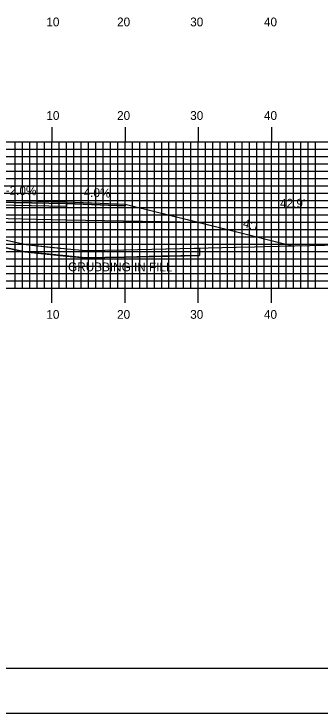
# Model space of a CAD drawing. Extents: x 1823573 to 1823916, y 442591 to 442811.
# Drawn here: x 1823743.1 to 1823784.9, y 442590.5 to 442686.2 of the extents above; entities that cross this region are included whole.
import ezdxf

# ---------------------------------------------------------------- set-up
doc = ezdxf.new("R2010")
doc.units = 0
for name, color, linetype in [('ANNOTATION', 7, 'Continuous'), ('BORDER', 7, 'Continuous'), ('D_Roadway_Centerline', 7, 'Continuous'), ('D_Roadway_Edge_Shoulder', 7, 'Continuous'), ('D_Roadway_Edge_TW', 7, 'Continuous'), ('D_Roadway_Pavement', 7, 'Continuous'), ('D_Roadway_SlopeLines', 7, 'Continuous'), ('D_Roadway_SubGrade', 7, 'Continuous'), ('D_Text_Standard', 7, 'Continuous'), ('GRUBBING IN FILL', 7, 'Continuous'), ('H_V ANNOTATION', 7, 'Continuous'), ('MAJOR', 7, 'Continuous'), ('MINOR', 7, 'Continuous'), ('PLOT BOUNDARY', 7, 'Continuous'), ('S_Roadway_Centerline', 7, 'Continuous')]:
    doc.layers.add(name, color=color, linetype=linetype)

msp = doc.modelspace()

# ---------------------------------------------------------------- linework, layer by layer
at = {"layer": 'BORDER'}
msp.add_lwpolyline([(1823588.709, 442596.665), (1823908.709, 442596.665), (1823908.709, 442806.665), (1823588.709, 442806.665)], close=True, dxfattribs=at)
at = {"layer": 'D_Roadway_Centerline'}
msp.add_lwpolyline([(1823662.489, 442655.78), (1823704.135, 442656.613), (1823708.135, 442657.613), (1823718.309, 442660.156), (1823726.309, 442660.476), (1823738.309, 442660.716), (1823750.309, 442660.476), (1823758.309, 442660.156), (1823768.483, 442657.613), (1823772.483, 442656.613), (1823781.16, 442654.443)], dxfattribs=at)
at = {"layer": 'D_Roadway_Edge_Shoulder'}
msp.add_lwpolyline([(1823750.309, 442660.476), (1823758.309, 442660.156), (1823758.309, 442659.906), (1823750.309, 442660.226)], close=True, dxfattribs=at)
at = {"layer": 'D_Roadway_Edge_TW'}
msp.add_lwpolyline([(1823726.309, 442660.226), (1823726.309, 442660.476), (1823738.309, 442660.716), (1823750.309, 442660.476), (1823750.309, 442660.226), (1823738.309, 442660.466)], close=True, dxfattribs=at)
at = {"layer": 'D_Roadway_Pavement'}
msp.add_lwpolyline([(1823726.309, 442659.81), (1823726.309, 442660.226), (1823738.309, 442660.466), (1823750.309, 442660.226), (1823750.309, 442659.81), (1823738.309, 442660.05)], close=True, dxfattribs=at)
at = {"layer": 'D_Roadway_SlopeLines'}
msp.add_lwpolyline([(1823758.309, 442660.156), (1823772.483, 442656.613), (1823781.16, 442654.443)], dxfattribs=at)
at = {"layer": 'D_Roadway_SubGrade'}
msp.add_lwpolyline([(1823726.309, 442657.976), (1823708.135, 442657.613), (1823718.309, 442660.156), (1823718.309, 442659.906), (1823726.309, 442660.226), (1823738.309, 442660.466), (1823750.309, 442660.226), (1823758.309, 442659.906), (1823758.309, 442660.156), (1823768.483, 442657.613), (1823750.309, 442657.976), (1823738.309, 442658.216)], close=True, dxfattribs=at)
at = {"layer": 'GRUBBING IN FILL'}
msp.add_line((1823768.483, 442654.139), (1823768.483, 442653.139), dxfattribs=at)
msp.add_line((1823768.483, 442654.139), (1823768.483, 442653.139), dxfattribs=at)
msp.add_lwpolyline([(1823726.758, 442657.985), (1823730.45, 442657.055), (1823735.693, 442655.836), (1823735.975, 442655.789), (1823737.608, 442655.298), (1823742.075, 442654.176), (1823744.635, 442653.625), (1823750.31, 442653.032), (1823752.893, 442652.796), (1823758.178, 442652.905), (1823768.483, 442653.139)], dxfattribs=at)
msp.add_lwpolyline([(1823726.758, 442657.985), (1823730.45, 442657.055), (1823735.693, 442655.836), (1823735.975, 442655.789), (1823737.608, 442655.298), (1823742.075, 442654.176), (1823744.635, 442653.625), (1823750.31, 442653.032), (1823752.893, 442652.796), (1823758.178, 442652.905), (1823768.483, 442653.139)], dxfattribs=at)
msp.add_lwpolyline([(1823738.309, 442656.153), (1823740.088, 442655.707), (1823742.302, 442655.15), (1823744.793, 442654.614), (1823747.6, 442654.321), (1823750.408, 442654.027), (1823752.928, 442653.797), (1823758.157, 442653.904), (1823765.827, 442654.079), (1823768.483, 442654.139), (1823768.483, 442653.139), (1823763.33, 442653.022), (1823758.178, 442652.905), (1823755.535, 442652.85), (1823752.893, 442652.796), (1823747.473, 442653.329), (1823744.635, 442653.625), (1823742.075, 442654.176), (1823738.309, 442655.122)], close=True, dxfattribs=at)
msp.add_lwpolyline([(1823738.309, 442656.153), (1823740.088, 442655.707), (1823742.302, 442655.15), (1823744.793, 442654.614), (1823747.6, 442654.321), (1823750.408, 442654.027), (1823752.928, 442653.797), (1823758.157, 442653.904), (1823765.827, 442654.079), (1823768.483, 442654.139), (1823768.483, 442653.139), (1823763.33, 442653.022), (1823758.178, 442652.905), (1823755.535, 442652.85), (1823752.893, 442652.796), (1823747.473, 442653.329), (1823744.635, 442653.625), (1823742.075, 442654.176), (1823738.309, 442655.122)], close=True, dxfattribs=at)
at = {"layer": 'MAJOR'}
for p, q in [((1823748.309, 442670.669), (1823748.309, 442668.665)), ((1823758.309, 442670.669), (1823758.309, 442668.665)), ((1823768.309, 442670.669), (1823768.309, 442668.665)), ((1823778.309, 442670.669), (1823778.309, 442668.665)), ((1823598.309, 442668.665), (1823878.309, 442668.665)), ((1823598.309, 442668.665), (1823878.309, 442668.665)), ((1823748.309, 442648.665), (1823748.309, 442668.665)), ((1823758.309, 442648.665), (1823758.309, 442668.665)), ((1823768.309, 442648.665), (1823768.309, 442668.665)), ((1823778.309, 442648.665), (1823778.309, 442668.665)), ((1823598.309, 442663.665), (1823878.309, 442663.665)), ((1823598.309, 442658.665), (1823878.309, 442658.665)), ((1823598.309, 442653.665), (1823878.309, 442653.665)), ((1823598.309, 442648.665), (1823878.309, 442648.665)), ((1823598.309, 442648.665), (1823878.309, 442648.665)), ((1823748.309, 442646.661), (1823748.309, 442648.665)), ((1823758.309, 442646.661), (1823758.309, 442648.665)), ((1823768.309, 442646.661), (1823768.309, 442648.665)), ((1823778.309, 442646.661), (1823778.309, 442648.665))]:
    msp.add_line(p, q, dxfattribs=at)
at = {"layer": 'MINOR'}
for p, q in [((1823743.309, 442648.665), (1823743.309, 442668.665)), ((1823744.309, 442648.665), (1823744.309, 442668.665)), ((1823745.309, 442648.665), (1823745.309, 442668.665)), ((1823746.309, 442648.665), (1823746.309, 442668.665)), ((1823747.309, 442648.665), (1823747.309, 442668.665)), ((1823749.309, 442648.665), (1823749.309, 442668.665)), ((1823750.309, 442648.665), (1823750.309, 442668.665)), ((1823751.309, 442648.665), (1823751.309, 442668.665)), ((1823752.309, 442648.665), (1823752.309, 442668.665)), ((1823753.309, 442648.665), (1823753.309, 442668.665)), ((1823754.309, 442648.665), (1823754.309, 442668.665)), ((1823755.309, 442648.665), (1823755.309, 442668.665)), ((1823756.309, 442648.665), (1823756.309, 442668.665)), ((1823757.309, 442648.665), (1823757.309, 442668.665)), ((1823759.309, 442648.665), (1823759.309, 442668.665)), ((1823760.309, 442648.665), (1823760.309, 442668.665)), ((1823761.309, 442648.665), (1823761.309, 442668.665)), ((1823762.309, 442648.665), (1823762.309, 442668.665)), ((1823763.309, 442648.665), (1823763.309, 442668.665)), ((1823764.309, 442648.665), (1823764.309, 442668.665)), ((1823765.309, 442648.665), (1823765.309, 442668.665)), ((1823766.309, 442648.665), (1823766.309, 442668.665)), ((1823767.309, 442648.665), (1823767.309, 442668.665)), ((1823769.309, 442648.665), (1823769.309, 442668.665)), ((1823770.309, 442648.665), (1823770.309, 442668.665)), ((1823771.309, 442648.665), (1823771.309, 442668.665)), ((1823772.309, 442648.665), (1823772.309, 442668.665)), ((1823773.309, 442648.665), (1823773.309, 442668.665)), ((1823774.309, 442648.665), (1823774.309, 442668.665)), ((1823775.309, 442648.665), (1823775.309, 442668.665)), ((1823776.309, 442648.665), (1823776.309, 442668.665)), ((1823777.309, 442648.665), (1823777.309, 442668.665)), ((1823779.309, 442648.665), (1823779.309, 442668.665)), ((1823780.309, 442648.665), (1823780.309, 442668.665)), ((1823781.309, 442648.665), (1823781.309, 442668.665)), ((1823782.309, 442648.665), (1823782.309, 442668.665)), ((1823783.309, 442648.665), (1823783.309, 442668.665)), ((1823784.309, 442648.665), (1823784.309, 442668.665)), ((1823598.309, 442667.665), (1823878.309, 442667.665)), ((1823598.309, 442666.665), (1823878.309, 442666.665)), ((1823598.309, 442665.665), (1823878.309, 442665.665)), ((1823598.309, 442664.665), (1823878.309, 442664.665)), ((1823598.309, 442662.665), (1823878.309, 442662.665)), ((1823598.309, 442661.665), (1823878.309, 442661.665)), ((1823598.309, 442660.665), (1823878.309, 442660.665)), ((1823598.309, 442659.665), (1823878.309, 442659.665)), ((1823598.309, 442657.665), (1823878.309, 442657.665)), ((1823598.309, 442656.665), (1823878.309, 442656.665)), ((1823598.309, 442655.665), (1823878.309, 442655.665)), ((1823598.309, 442654.665), (1823878.309, 442654.665)), ((1823598.309, 442652.665), (1823878.309, 442652.665)), ((1823598.309, 442651.665), (1823878.309, 442651.665)), ((1823598.309, 442650.665), (1823878.309, 442650.665)), ((1823598.309, 442649.665), (1823878.309, 442649.665))]:
    msp.add_line(p, q, dxfattribs=at)
at = {"layer": 'PLOT BOUNDARY'}
msp.add_lwpolyline([(1823572.522, 442590.547), (1823912.522, 442590.547), (1823912.522, 442810.547), (1823572.522, 442810.547)], close=True, dxfattribs=at)
at = {"layer": 'S_Roadway_Centerline'}
msp.add_lwpolyline([(1823742.302, 442655.15), (1823744.793, 442654.614), (1823750.408, 442654.027), (1823752.928, 442653.797), (1823758.157, 442653.904), (1823773.497, 442654.254), (1823776.009, 442654.309), (1823777.313, 442654.356), (1823793.941, 442654.733)], dxfattribs=at)

# ---------------------------------------------------------------- texts
at = {"layer": 'ANNOTATION'}
for s, rotation, p in [('-2.0%', 358.85424, (1823741.995, 442661.443)), ('-4.0%', 357.70939, (1823752.1, 442661.206)), ('4:1', 345.96376, (1823774.327, 442657.013))]:
    msp.add_text(s, height=1.2, rotation=rotation, dxfattribs=at).set_placement(p)
at = {"layer": 'D_Text_Standard'}
msp.add_text("42.9'", height=1.2, dxfattribs=at).set_placement((1823779.475, 442659.67))
at = {"layer": 'GRUBBING IN FILL'}
msp.add_text('GRUBBING IN FILL', height=1.2, rotation=359.80532, dxfattribs=at).set_placement((1823750.523, 442650.981))
at = {"layer": 'H_V ANNOTATION'}
for s, p in [('10', (1823747.559, 442684.465)), ('20', (1823757.217, 442684.465)), ('30', (1823767.206, 442684.465)), ('40', (1823777.281, 442684.465)), ('10', (1823747.559, 442671.665)), ('20', (1823757.217, 442671.665)), ('30', (1823767.206, 442671.665)), ('40', (1823777.281, 442671.665)), ('10', (1823747.559, 442644.465)), ('20', (1823757.217, 442644.465)), ('30', (1823767.206, 442644.465)), ('40', (1823777.281, 442644.465))]:
    msp.add_text(s, height=1.2, dxfattribs=at).set_placement(p)

doc.saveas('drawing.dxf')
